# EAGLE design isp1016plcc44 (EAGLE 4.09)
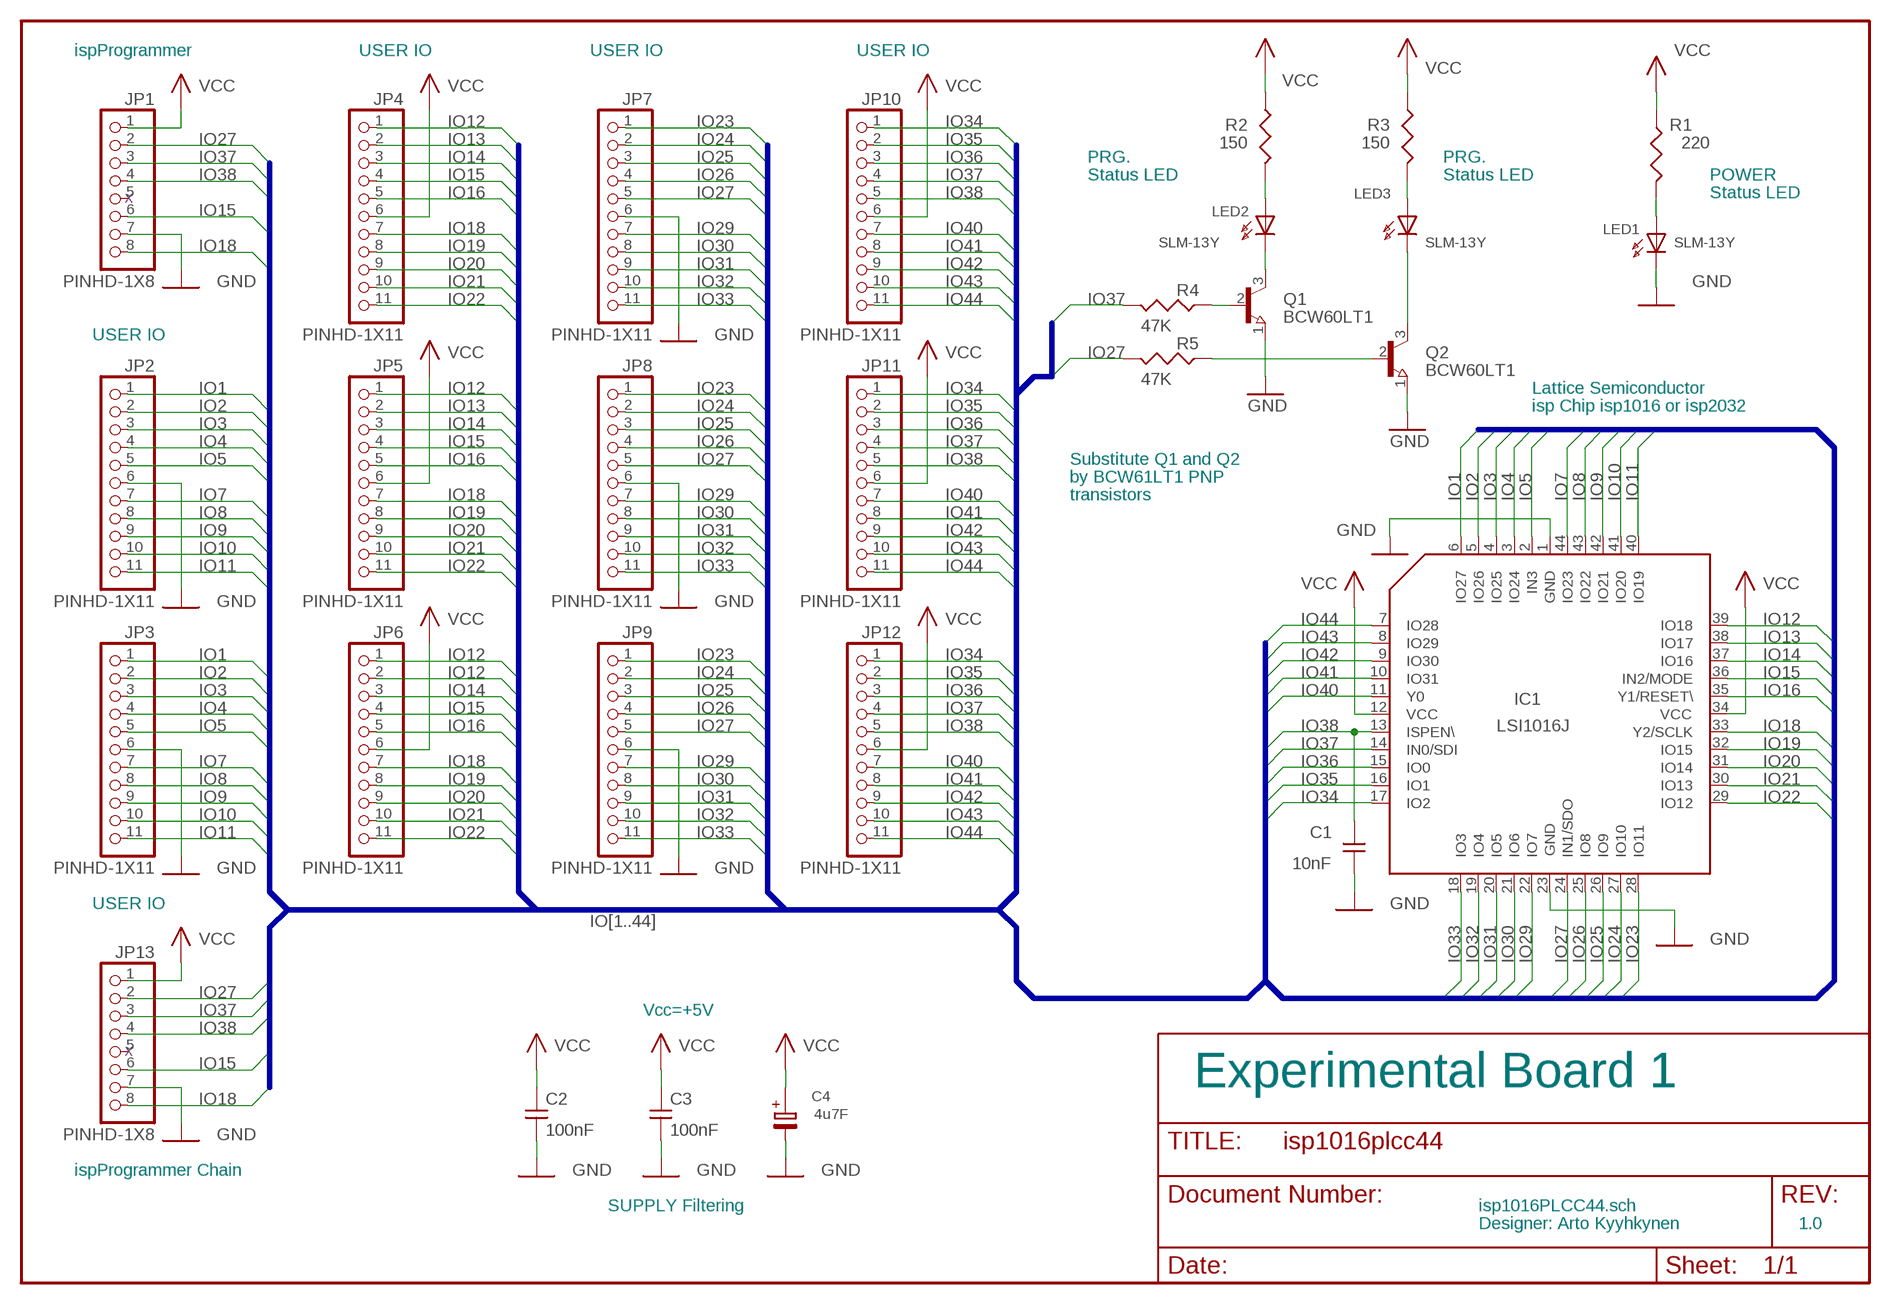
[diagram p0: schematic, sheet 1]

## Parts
C1  10nF  CAP0603  [SMD0603]
C2  100nF  CAP0603  [SMD0603]
C3  100nF  CAP0603  [SMD0603]
C4  4u7F  CAP1210  [SMD1210]
IC1  LSI1016J  [PLCC44]
JP1  PINHD-1X8  [SIL8]
JP2  PINHD-1X11  [SIL11]
JP3  PINHD-1X11  [SIL11]
JP4  PINHD-1X11  [SIL11]
JP5  PINHD-1X11  [SIL11]
JP6  PINHD-1X11  [SIL11]
JP7  PINHD-1X11  [SIL11]
JP8  PINHD-1X11  [SIL11]
JP9  PINHD-1X11  [SIL11]
JP10  PINHD-1X11  [SIL11]
JP11  PINHD-1X11  [SIL11]
JP12  PINHD-1X11  [SIL11]
JP13  PINHD-1X8  [SIL8]
LED1  SLM-13Y  LEDSOT23  [SOT23]
LED2  SLM-13Y  LEDSOT23  [SOT23]
LED3  SLM-13Y  LEDSOT23  [SOT23]
Q1  BCW60LT1  [SOT23]
Q2  BCW60LT1  [SOT23]
R1  220  RES0603  [SMD0603]
R2  150  RES0603  [SMD0603]
R3  150  RES0603  [SMD0603]
R4  47K  RES0603  [SMD0603]
R5  47K  RES0603  [SMD0603]

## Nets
GND: C1.1 C2.1 C3.1 C4.2(-) IC1.1(GND) IC1.23(GND) JP1.7 JP2.6 JP3.6 JP7.6 JP8.6 JP9.6 JP13.7 LED1.3(K) Q1.1(E) Q2.1(E)
IO1: IC1.6(IO27) JP2.1 JP3.1
IO2: IC1.5(IO26) JP2.2 JP3.2
IO3: IC1.4(IO25) JP2.3 JP3.3
IO4: IC1.3(IO24) JP2.4 JP3.4
IO5: IC1.2(IN3) JP2.5 JP3.5
IO7: IC1.44(IO23) JP2.7 JP3.7
IO8: IC1.43(IO22) JP2.8 JP3.8
IO9: IC1.42(IO21) JP2.9 JP3.9
IO10: IC1.41(IO20) JP2.10 JP3.10
IO11: IC1.40(IO19) JP2.11 JP3.11
IO12: IC1.39(IO18) JP4.1 JP5.1 JP6.1
IO13: IC1.38(IO17) JP4.2 JP5.2 JP6.2
IO14: IC1.37(IO16) JP4.3 JP5.3 JP6.3
IO15: IC1.36(IN2/MODE) JP1.6 JP4.4 JP5.4 JP6.4 JP13.6
IO16: IC1.35(Y1/RESET\) JP4.5 JP5.5 JP6.5
IO18: IC1.33(Y2/SCLK) JP1.8 JP4.7 JP5.7 JP6.7 JP13.8
IO19: IC1.32(IO15) JP4.8 JP5.8 JP6.8
IO20: IC1.31(IO14) JP4.9 JP5.9 JP6.9
IO21: IC1.30(IO13) JP4.10 JP5.10 JP6.10
IO22: IC1.29(IO12) JP4.11 JP5.11 JP6.11
IO23: IC1.28(IO11) JP7.1 JP8.1 JP9.1
IO24: IC1.27(IO10) JP7.2 JP8.2 JP9.2
IO25: IC1.26(IO9) JP7.3 JP8.3 JP9.3
IO26: IC1.25(IO8) JP7.4 JP8.4 JP9.4
IO27: IC1.24(IN1/SDO) JP1.2 JP7.5 JP8.5 JP9.5 JP13.2 R5.2
IO29: IC1.22(IO7) JP7.7 JP8.7 JP9.7
IO30: IC1.21(IO6) JP7.8 JP8.8 JP9.8
IO31: IC1.20(IO5) JP7.9 JP8.9 JP9.9
IO32: IC1.19(IO4) JP7.10 JP8.10 JP9.10
IO33: IC1.18(IO3) JP7.11 JP8.11 JP9.11
IO34: IC1.17(IO2) JP10.1 JP11.1 JP12.1
IO35: IC1.16(IO1) JP10.2 JP11.2 JP12.2
IO36: IC1.15(IO0) JP10.3 JP11.3 JP12.3
IO37: IC1.14(IN0/SDI) JP1.3 JP10.4 JP11.4 JP12.4 JP13.3 R4.2
IO38: C1.2 IC1.13(ISPEN\) JP1.4 JP10.5 JP11.5 JP12.5 JP13.4
IO40: IC1.11(Y0) JP10.7 JP11.7 JP12.7
IO41: IC1.10(IO31) JP10.8 JP11.8 JP12.8
IO42: IC1.9(IO30) JP10.9 JP11.9 JP12.9
IO43: IC1.8(IO29) JP10.10 JP11.10 JP12.10
IO44: IC1.7(IO28) JP10.11 JP11.11 JP12.11
N$1: LED1.2(A) R1.2
N$2: LED3.2(A) R3.2
N$3: LED2.2(A) R2.2
N$4: LED2.3(K) Q1.3(C)
N$5: LED3.3(K) Q2.3(C)
N$6: Q1.2(B) R4.1
N$7: Q2.2(B) R5.1
VCC: C2.2 C3.2 C4.1(+) IC1.12(VCC) IC1.34(VCC) JP1.1 JP4.6 JP5.6 JP6.6 JP10.6 JP11.6 JP12.6 JP13.1 R1.1 R2.1 R3.1
Unconnected: JP1.5 JP13.5

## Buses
IO[1..44]

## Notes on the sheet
- ispProgrammer | USER IO | USER IO | USER IO
- PRG. | PRG.
- Status LED | Status LED | POWER
- Status LED
- X
- USER IO
- Lattice Semiconductor
- isp Chip isp1016 or isp2032
- Substitute Q1 and Q2
- by BCW61LT1 PNP
- transistors
- USER IO
- Vcc=+5V
- X
- Experimental Board 1
- ispProgrammer Chain
- SUPPLY Filtering | isp1016PLCC44.sch
- Designer: Arto Kyyhkynen | 1.0

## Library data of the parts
C1-C3 = user1:CAP0603
C4 = user1:CAP1210
IC1 = lattice:LSI1016J
JP1 JP13 = pinhead:PINHD-1X8
JP2-JP12 = pinhead:PINHD-1X11
LED1-LED3 = user1:LEDSOT23
Q1 Q2 = user1:BCW60LT1
R1-R5 = user1:RES0603: SMD resistor

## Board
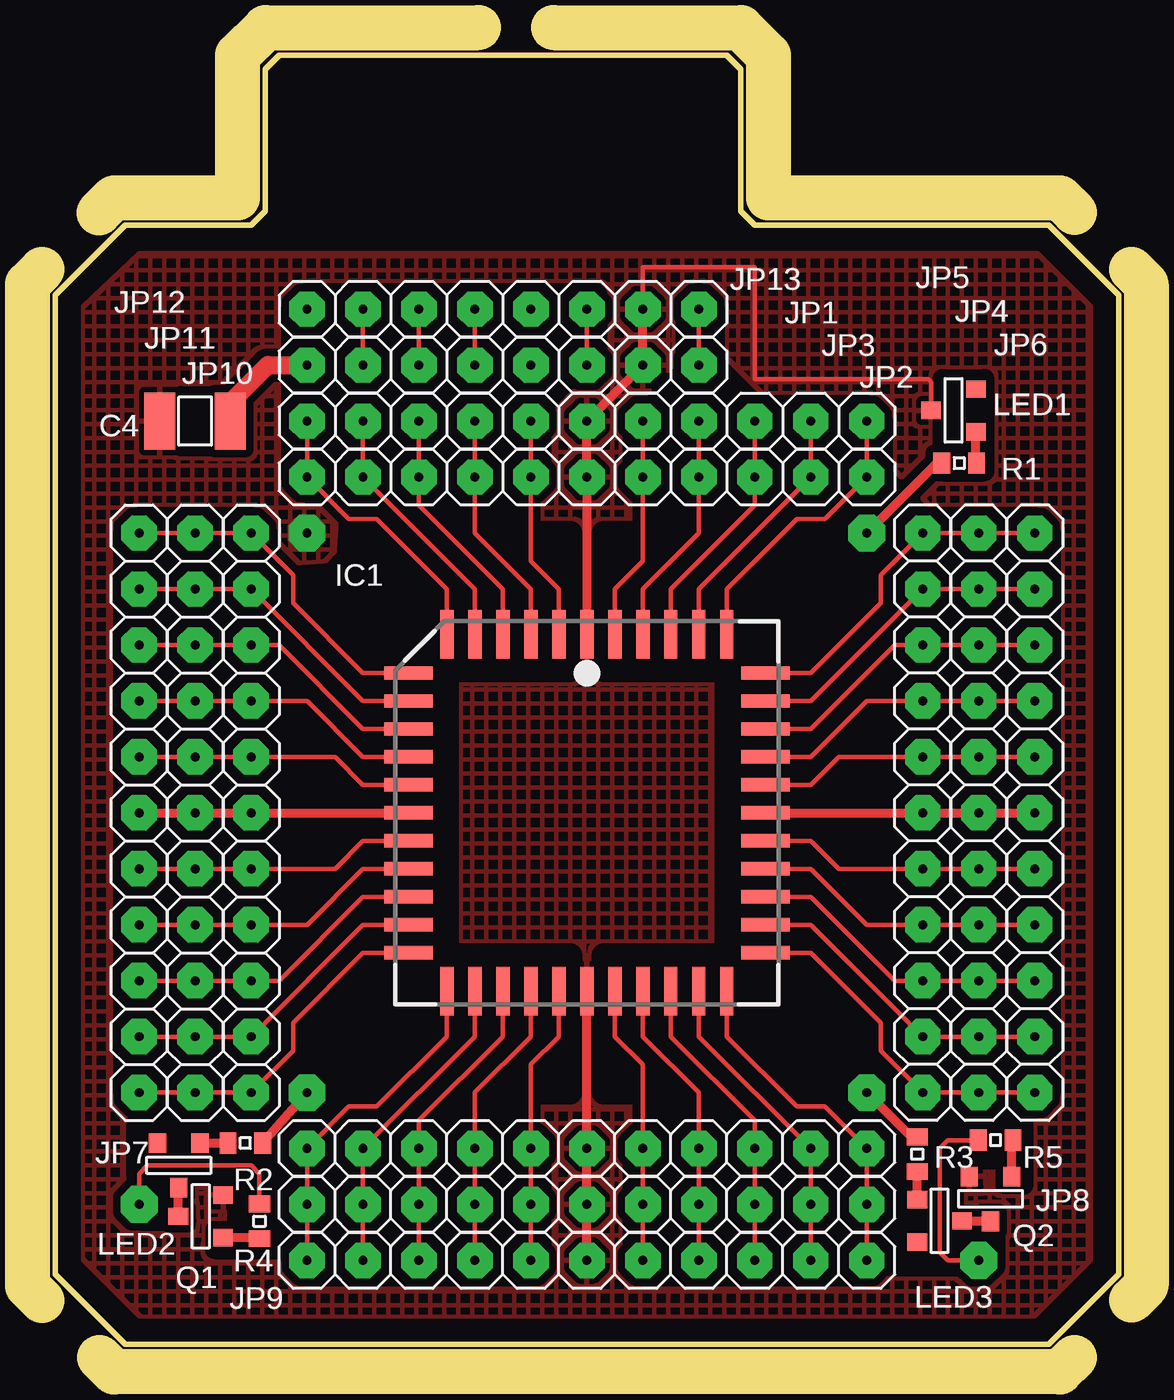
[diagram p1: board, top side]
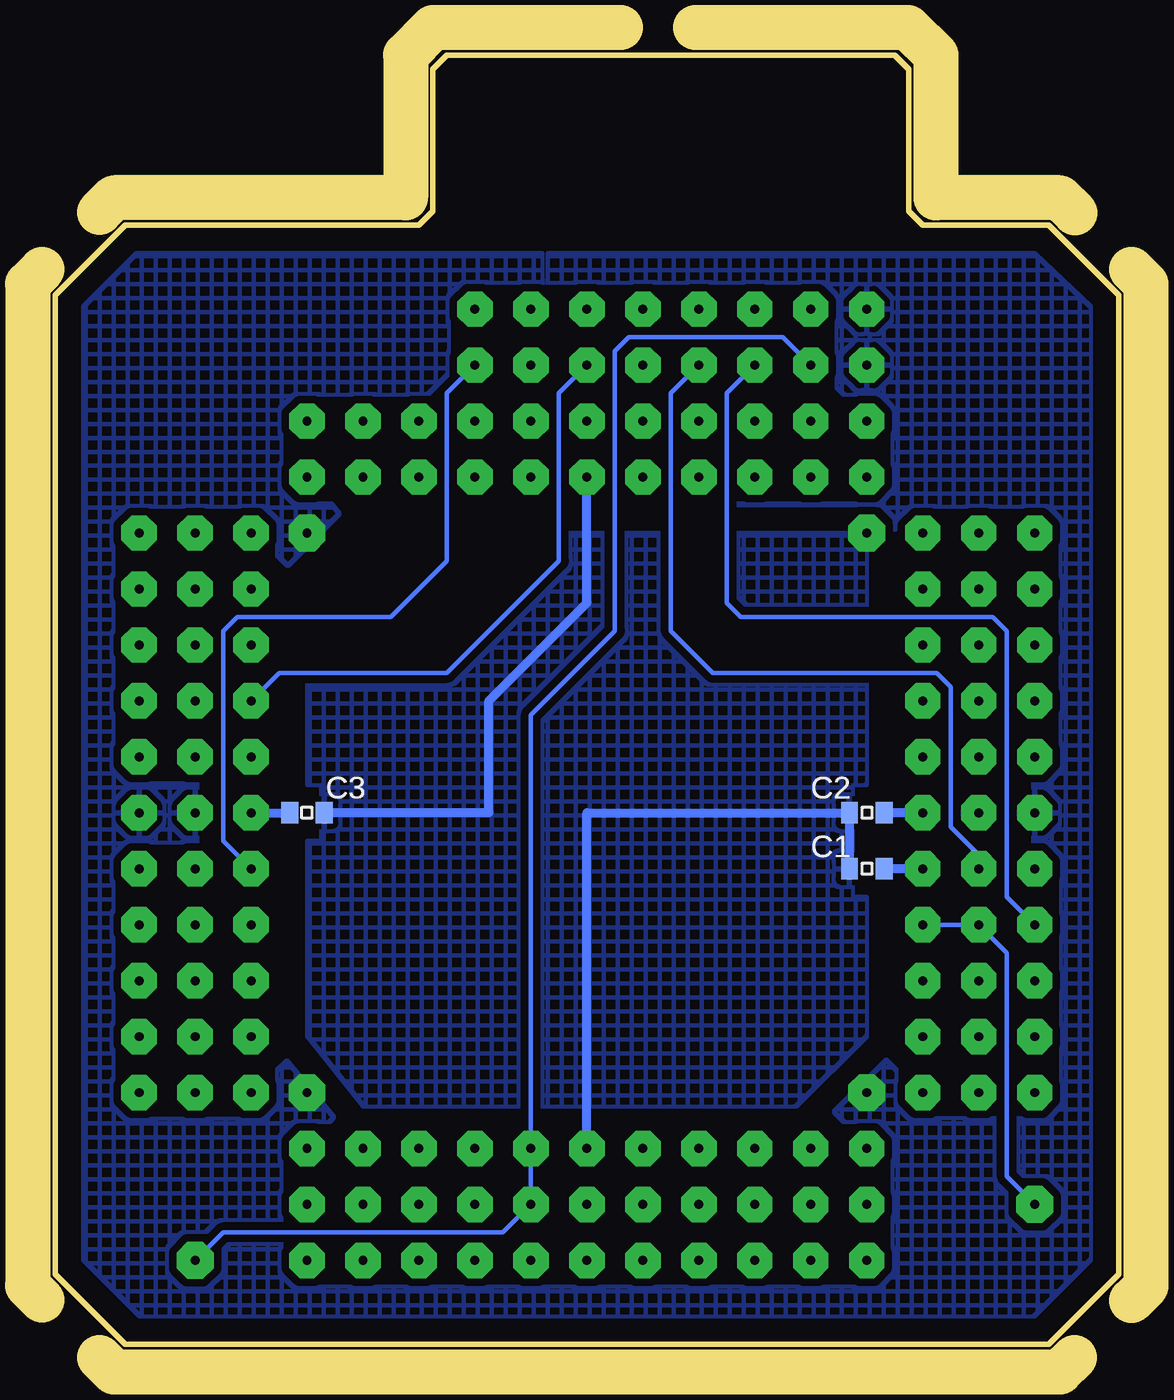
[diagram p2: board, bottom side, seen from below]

Size 48.26 x 58.52 mm. Coordinates in mm from the lower left corner, seen from the top.
Outline: 45.09,50.8 48.26,47.62 48.26,3.17 45.09,0 3.17,0 0,3.17 0,47.62 3.17,50.8 8.89,50.8 9.53,51.43 9.53,57.89 10.16,58.52 30.48,58.52 31.11,57.89 31.11,51.43 31.75,50.8 45.09,50.8
Copper layers used: Top, Bottom
tRestrict: 105 lines
bRestrict: 74 lines
Milling: 19 lines

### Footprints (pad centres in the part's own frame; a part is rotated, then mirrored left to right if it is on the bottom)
SMD0603 = smd 0.762 x 0.965: 1 -0.787,0; 2 0.787,0
SMD1210 = smd 1.397 x 2.591: 1 -1.6,0; 2 1.6,0
PLCC44 = smd 0.6 x 2.2: 1 0,8.1; 2 -1.27,8.1; 3 -2.54,8.1; 4 -3.81,8.1; 5 -5.08,8.1; 6 -6.35,8.1; 18 -6.35,-8.1; 19 -5.08,-8.1; 20 -3.81,-8.1; 21 -2.54,-8.1; 22 -1.27,-8.1; 23 0,-8.1; 24 1.27,-8.1; 25 2.54,-8.1; 26 3.81,-8.1; 27 5.08,-8.1; 28 6.35,-8.1; 40 6.35,8.1; 41 5.08,8.1; 42 3.81,8.1; 43 2.54,8.1; 44 1.27,8.1 | smd 2.2 x 0.6: 7 -8.1,6.35; 8 -8.1,5.08; 9 -8.1,3.81; 10 -8.1,2.54; 11 -8.1,1.27; 12 -8.1,0; 13 -8.1,-1.27; 14 -8.1,-2.54; 15 -8.1,-3.81; 16 -8.1,-5.08; 17 -8.1,-6.35; 29 8.1,-6.35; 30 8.1,-5.08; 31 8.1,-3.81; 32 8.1,-2.54; 33 8.1,-1.27; 34 8.1,0; 35 8.1,1.27; 36 8.1,2.54; 37 8.1,3.81; 38 8.1,5.08; 39 8.1,6.35
SIL8 = drill 0.406 pad 1.6 octagon: 1 -8.89,0; 2 -6.35,0; 3 -3.81,0; 4 -1.27,0; 5 1.27,0; 6 3.81,0; 7 6.35,0; 8 8.89,0
SIL11 = drill 0.406 pad 1.6 octagon: 1 -12.7,0; 2 -10.16,0; 3 -7.62,0; 4 -5.08,0; 5 -2.54,0; 6 0,0; 7 2.54,0; 8 5.08,0; 9 7.62,0; 10 10.16,0; 11 12.7,0
SOT23 = smd 0.787 x 0.889: 1 -0.94,1.016; 2 0.991,1.016; 3 0.025,-1.016

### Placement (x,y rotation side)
C1  11.43,21.59 0 bottom
C2  11.43,24.13 0 bottom
C3  36.83,24.13 180 bottom
C4  6.35,41.91 180 top
IC1  24.13,24.13 0 top
JP1  20.32,44.45 0 top
JP2  24.13,39.37 0 top
JP3  24.13,41.91 0 top
JP4  41.91,24.13 270 top
JP5  44.45,24.13 270 top
JP6  39.37,24.13 270 top
JP7  24.13,8.89 180 top
JP8  24.13,6.35 180 top
JP9  24.13,3.81 180 top
JP10  8.89,24.13 90 top
JP11  6.35,24.13 90 top
JP12  3.81,24.13 90 top
JP13  20.32,46.99 0 top
LED1  40.77,42.42 270 top
LED2  5.59,8.13 0 top
LED3  40.13,5.59 90 top
Q1  6.6,5.84 270 top
Q2  42.42,6.6 0 top
R1  41.02,40 0 top
R2  8.64,9.14 180 top
R3  39.12,8.64 270 top
R4  9.27,5.59 90 top
R5  42.67,9.27 180 top

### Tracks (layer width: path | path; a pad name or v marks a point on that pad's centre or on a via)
GND  (via drill 0.41 pad 1.68)
  Top 0.203: LED1.3 39.75,43.69 39.62,43.81 31.75,43.81 31.75,48.89 26.67,48.89 JP13.7
  Top 0.406: 24.13,15.88 JP7.6 JP8.6 JP9.6 | 24.13,32.13 IC1.1 JP2.6 JP3.6 JP1.7 JP13.7
  Bottom 0.406: C1.1 12.06,21.59 12.22,21.74 C2.1 | C2.1 12.06,24.13 | JP2.6 24.13,33.66 28.58,29.21 28.58,24.13 C3.1 | JP7.6 24.13,24.13 C2.1
  other vias: 11.43,36.83
  pour Top (isolate 0.356, hatched): 44.58,49.53 46.99,47.12 46.99,3.81 44.45,1.27 3.81,1.27 1.27,3.81 1.27,47.12 3.81,49.53
  pour Bottom (isolate 0.356, hatched): 11.43,36.83 34.29,36.83 36.83,34.29 36.83,25.4 36.2,25.4 36.2,22.86 36.83,22.86 36.83,13.97 34.29,10.79 14.6,10.79 11.43,13.97 11.43,20.32 12.06,20.32 12.06,25.4 11.43,25.4
IO1
  Top 0.203: JP3.1 JP2.1 13.33,37.46 14.6,37.46 17.78,34.29 IC1.6
IO2
  Top 0.203: JP3.2 JP2.2 19.05,34.29 IC1.5
IO3
  Top 0.203: JP3.3 JP2.3 16.51,38.1 20.32,34.29 IC1.4
IO4
  Top 0.203: JP3.4 JP2.4 19.05,36.83 21.59,34.29 IC1.3
IO5
  Top 0.203: JP3.5 JP2.5 21.59,35.56 22.86,34.29 IC1.2
IO7
  Top 0.203: JP3.7 JP2.7 26.67,35.56 25.4,34.29 IC1.44
IO8
  Top 0.203: JP3.8 JP2.8 29.21,36.83 26.67,34.29 IC1.43
IO9
  Top 0.203: JP3.9 JP2.9 31.75,38.1 27.94,34.29 IC1.42
IO10
  Top 0.203: JP3.10 JP2.10 29.21,34.29 IC1.41
IO11
  Top 0.203: JP3.11 JP2.11 34.92,37.46 33.66,37.46 30.48,34.29 IC1.40
IO12
  Top 0.203: JP5.1 JP4.1 JP6.1 37.46,34.92 37.46,33.66 34.29,30.48 IC1.39
IO13
  Top 0.203: IC1.38 34.29,29.21 JP6.2 JP4.2 JP5.2
IO14
  Top 0.203: IC1.37 34.29,27.94 38.1,31.75 JP6.3 JP4.3 JP5.3
IO15
  Top 0.203: IC1.36 34.29,26.67 36.83,29.21 JP6.4 JP4.4 JP5.4 | JP1.6 JP13.6
  Bottom 0.203: JP1.6 25.4,43.18 25.4,35.56 30.48,30.48 38.1,30.48 JP6.4
IO16
  Top 0.203: IC1.35 34.29,25.4 35.56,26.67 JP6.5 JP4.5 JP5.5
IO18
  Top 0.203: IC1.33 34.29,22.86 35.56,21.59 JP6.7 JP4.7 JP5.7 | JP1.8 JP13.8
  Bottom 0.203: JP1.8 30.48,43.18 30.48,35.56 33.02,33.02 40,33.02 40.64,32.38 40.64,22.86 JP6.7
IO19
  Top 0.203: IC1.32 34.29,21.59 36.83,19.05 JP6.8 JP4.8 JP5.8
IO20
  Top 0.203: IC1.31 34.29,20.32 38.1,16.51 JP6.9 JP4.9 JP5.9
IO21
  Top 0.203: IC1.30 34.29,19.05 JP6.10 JP4.10 JP5.10
IO22
  Top 0.203: IC1.29 34.29,17.78 37.46,14.6 37.46,13.33 JP6.11 JP4.11 JP5.11
IO23
  Top 0.203: IC1.28 30.48,13.97 33.66,10.79 34.92,10.79 JP7.1 JP8.1 JP9.1
IO24
  Top 0.203: IC1.27 29.21,13.97 JP7.2 JP8.2 JP9.2
IO25
  Top 0.203: IC1.26 27.94,13.97 31.75,10.16 JP7.3 JP8.3 JP9.3
IO26
  Top 0.203: IC1.25 26.67,13.97 29.21,11.43 JP7.4 JP8.4 JP9.4
IO27  (via drill 0.41 pad 1.68)
  Top 0.203: IC1.24 25.4,13.97 26.67,12.7 JP7.5 JP8.5 JP9.5 | R5.2 40.51,9.27 40.13,8.89 40.13,4.19 40.51,3.81 v41.91,3.81 | JP1.2 JP13.2
  Bottom 0.203: v41.91,3.81 40.64,5.08 27.94,5.08 JP8.5 JP7.5 26.67,28.58 22.86,32.38 22.86,45.09 22.23,45.72 15.24,45.72 JP1.2
IO29
  Top 0.203: IC1.22 22.86,13.97 21.59,12.7 JP7.7 JP8.7 JP9.7
IO30
  Top 0.203: IC1.21 21.59,13.97 19.05,11.43 JP7.8 JP8.8 JP9.8
IO31
  Top 0.203: IC1.20 20.32,13.97 16.51,10.16 JP7.9 JP8.9 JP9.9
IO32
  Top 0.203: IC1.19 19.05,13.97 JP7.10 JP8.10 JP9.10
IO33
  Top 0.203: IC1.18 17.78,13.97 14.6,10.79 13.33,10.79 JP7.11 JP8.11 JP9.11
IO34
  Top 0.203: IC1.17 13.97,17.78 10.79,14.6 10.79,13.33 JP10.1 JP11.1 JP12.1
IO35
  Top 0.203: IC1.16 13.97,19.05 JP10.2 JP11.2 JP12.2
IO36
  Top 0.203: IC1.15 13.97,20.32 10.16,16.51 JP10.3 JP11.3 JP12.3
IO37  (via drill 0.41 pad 1.68)
  Top 0.203: IC1.14 13.97,21.59 11.43,19.05 JP10.4 JP11.4 JP12.4 | R4.2 9.27,7.75 8.89,8.13 4.19,8.13 3.81,7.75 v3.81,6.35 | JP1.3 JP13.3
  Bottom 0.203: JP10.4 JP11.4 5.08,17.78 5.08,7.62 v3.81,6.35 | JP1.3 17.78,43.18 17.78,33.66 17.15,33.02 5.71,33.02 5.08,32.38 5.08,20.32 JP12.4
IO38
  Top 0.203: IC1.13 13.97,22.86 12.7,21.59 JP10.5 JP11.5 JP12.5 | JP1.4 JP13.4
  Bottom 0.203: JP1.4 20.32,43.18 20.32,32.38 18.41,30.48 8.26,30.48 7.62,29.84 7.62,23.49 6.35,22.23 JP11.5
  Bottom 0.406: JP10.5 C1.2
IO40
  Top 0.203: IC1.11 13.97,25.4 12.7,26.67 JP10.7 JP11.7 JP12.7
IO41
  Top 0.203: IC1.10 13.97,26.67 11.43,29.21 JP10.8 JP11.8 JP12.8
IO42
  Top 0.203: IC1.9 13.97,27.94 10.16,31.75 JP10.9 JP11.9 JP12.9
IO43
  Top 0.203: IC1.8 13.97,29.21 JP10.10 JP11.10 JP12.10
IO44
  Top 0.203: IC1.7 13.97,30.48 10.79,33.66 10.79,34.92 JP10.11 JP11.11 JP12.11
N$1
  Top 0.406: R1.2 41.81,39.9 41.78,39.88 LED1.2
N$2
  Top 0.406: 39.12,7.87 R3.2 LED3.2
N$3
  Top 0.406: 8,9.14 R2.2 LED2.2
N$4
  Top 0.406: LED2.3 5.59,7.11 Q1.3
N$5
  Top 0.406: LED3.3 41.15,5.71 41.27,5.59 Q2.3
N$6
  Top 0.406: R4.1 9.27,4.83 9.25,4.85 Q1.2
N$7
  Top 0.406: R5.1 43.43,9.27 43.41,9.25 Q2.2
VCC  (via drill 0.41 pad 1.68)
  Top 0.406: R3.1 38.84,9.42 v36.83,11.43 | R1.1 40,40 v36.83,36.83 | 31.75,24.13 IC1.34 JP6.6 JP4.6 JP5.6 | R2.1 v11.43,11.43 | IC1.12 JP10.6 JP11.6 JP12.6
  Top 0.813: C4.1 7.95,42.75 9.65,44.45 JP1.1
  Bottom 0.203: 10.79,24.13 C2.2 JP10.6
  Bottom 0.406: JP6.6 C3.2 | JP10.6 C2.2
  pour Bottom (isolate 0.356, hatched): 26.16,49.53 26.04,38.1 34.92,38.1 38.1,34.92 38.1,13.33 34.92,9.53 13.97,9.53 10.16,13.33 10.16,37.46 10.79,38.1 25.91,38.1 25.91,49.53 3.81,49.53 1.27,47.12 1.27,3.81 3.81,1.27 44.45,1.27 46.99,3.81 46.99,47.12 44.58,49.53

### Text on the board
_tNames: JP13 | JP5 | JP12 | JP11 | JP1 | JP4 | JP3 | JP6 | JP10 | JP2 | C4 | LED1 | R1 | IC1 | JP7 | R5 | R2 | R3 | JP8 | LED2 | R4 | Q2 | Q1 | JP9 | LED3
_bNames: C3 | C2 | C1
